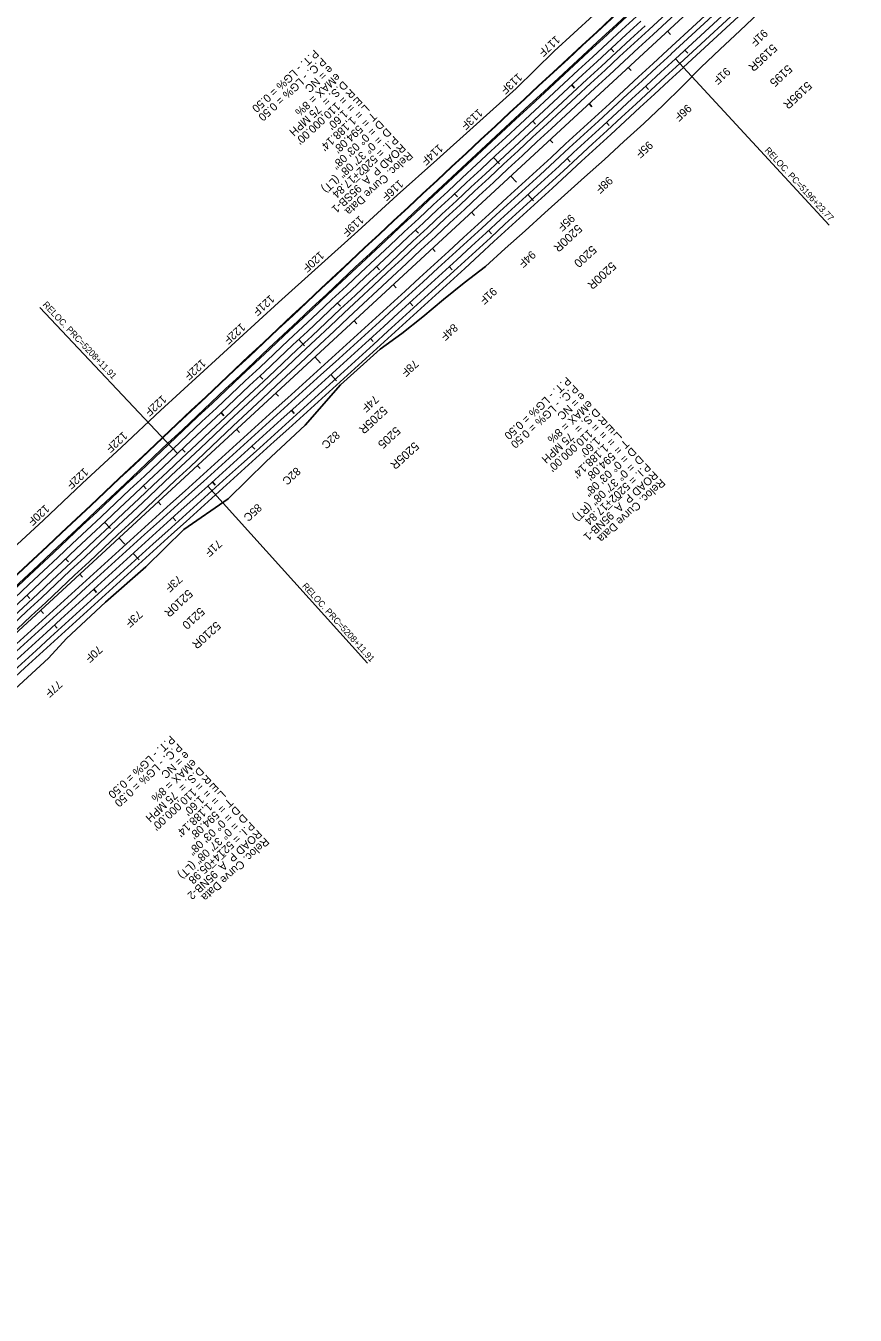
# Model space of a CAD drawing. Extents: x 2160876 to 2175625, y 601634 to 617693.
# Drawn here: x 2169242 to 2170797, y 609675 to 612093 of the extents above; entities that cross this region are included whole.
import ezdxf

# ---------------------------------------------------------------- set-up
doc = ezdxf.new("R2010")
doc.units = 0
for name, color, linetype in [('RD_HC_Cl', 7, 'Continuous'), ('RD_HC_CL_Rel', 7, 'Continuous'), ('RD_HC_Data_Rel', 7, 'Continuous'), ('RD_HC_Data_Tic', 7, 'Continuous'), ('RD_HC_Data_Tic_Rel', 7, 'Continuous'), ('RD_HC_TX_Rel_Sta50', 7, 'Continuous'), ('RD_HC_TX_Sta50', 7, 'Continuous'), ('RD_PD_CstnLmt', 7, 'Continuous'), ('RD_PD_Final_LnLine', 7, 'Continuous'), ('RD_PD_Final_TrvlWay', 7, 'Continuous'), ('RD_PD_GR', 7, 'Continuous'), ('RD_PD_MedBWall', 7, 'Continuous')]:
    doc.layers.add(name, color=color, linetype=linetype)

msp = doc.modelspace()

# ---------------------------------------------------------------- linework, layer by layer
at = {"layer": 'RD_HC_Cl'}
msp.add_line((2172239.9, 613739.9), (2163704.8, 605858.6), dxfattribs=at)
at = {"layer": 'RD_HC_CL_Rel'}
msp.add_line((2172272.5, 613704.6), (2170460.3, 612031.3), dxfattribs=at)
for centre, start, end in [((2245020.2, 531286.6), 132.719474, 133.338342), ((2095835.3, 692846.5), 312.100607, 312.719474), ((2094033.1, 691295.6), 312.719474, 313.338342), ((2243330.9, 529613.4), 132.100607, 132.719474)]:
    msp.add_arc(centre, 110000, start, end, dxfattribs=at)
at = {"layer": 'RD_HC_Data_Rel'}
for p, q in [((2170748.5, 611719.1), (2170460.3, 612031.3)), ((2169268.2, 611565), (2169526.6, 611291.1)), ((2169883, 610898), (2169583.1, 611230))]:
    msp.add_line(p, q, dxfattribs=at)
at = {"layer": 'RD_HC_Data_Tic'}
for p, q in [((2170445.2, 612082.7), (2170450.6, 612076.8)), ((2170371.7, 612014.8), (2170377.2, 612008.9)), ((2170298.3, 611947), (2170303.7, 611941.1)), ((2170224.8, 611879.1), (2170230.2, 611873.3)), ((2170151.3, 611811.3), (2170162.2, 611799.5)), ((2170077.9, 611743.5), (2170083.3, 611737.6)), ((2170004.4, 611675.6), (2170009.8, 611669.7)), ((2169930.9, 611607.8), (2169936.3, 611601.9)), ((2169857.5, 611539.9), (2169862.9, 611534.1)), ((2169784, 611472.1), (2169794.8, 611460.3)), ((2169710.5, 611404.2), (2169715.9, 611398.4)), ((2169637, 611336.4), (2169642.5, 611330.5)), ((2169563.6, 611268.6), (2169569, 611262.7)), ((2169490.1, 611200.7), (2169495.5, 611194.8)), ((2169416.6, 611132.9), (2169427.5, 611121.1)), ((2169343.2, 611065), (2169348.6, 611059.2)), ((2169269.7, 610997.2), (2169275.1, 610991.3))]:
    msp.add_line(p, q, dxfattribs=at)
at = {"layer": 'RD_HC_Data_Tic_Rel'}
for p, q in [((2170339.2, 612050.1), (2170344.6, 612044.2)), ((2170477.8, 612047.4), (2170483.2, 612041.5)), ((2170265.8, 611982.1), (2170271.2, 611976.3)), ((2170404.3, 611979.6), (2170409.7, 611973.7)), ((2170192.5, 611914.1), (2170197.9, 611908.3)), ((2170330.7, 611911.8), (2170336.2, 611905.9)), ((2170119.2, 611846.1), (2170130.1, 611834.4)), ((2170257.1, 611844.1), (2170262.5, 611838.2)), ((2170046, 611778), (2170051.4, 611772.1)), ((2170183.5, 611776.5), (2170194.3, 611764.7)), ((2169972.9, 611709.8), (2169978.3, 611703.9)), ((2170109.7, 611708.9), (2170115.1, 611703)), ((2169899.8, 611641.5), (2169905.2, 611635.7)), ((2170035.9, 611641.5), (2170041.3, 611635.6)), ((2169826.8, 611573.2), (2169832.2, 611567.3)), ((2169962.1, 611574), (2169967.5, 611568.1)), ((2169753.8, 611504.8), (2169764.7, 611493.1)), ((2169888.2, 611506.7), (2169893.6, 611500.8)), ((2169814.2, 611439.4), (2169824.9, 611427.6)), ((2169680.9, 611436.3), (2169686.4, 611430.5)), ((2169608.1, 611367.8), (2169613.6, 611362)), ((2169740.2, 611372.2), (2169745.5, 611366.3)), ((2169535.3, 611299.2), (2169540.8, 611293.4)), ((2169666.1, 611305), (2169671.4, 611299.1)), ((2169462.5, 611230.6), (2169468, 611224.8)), ((2169591.9, 611237.9), (2169597.3, 611232)), ((2169517.7, 611170.9), (2169523.1, 611164.9)), ((2169389.7, 611162.1), (2169400.7, 611150.4)), ((2169443.6, 611103.7), (2169454.4, 611091.9)), ((2169316.8, 611093.6), (2169322.3, 611087.8)), ((2169369.6, 611036.5), (2169374.9, 611030.6)), ((2169243.9, 611025.2), (2169249.4, 611019.4)), ((2169295.6, 610969.3), (2169301, 610963.3))]:
    msp.add_line(p, q, dxfattribs=at)
at = {"layer": 'RD_PD_CstnLmt'}
for p, q in [((2170306.3, 612112.7), (2170232.5, 612045.5)), ((2170232.5, 612045.5), (2170161.6, 611975.2)), ((2170161.6, 611975.2), (2170087.4, 611908.3)), ((2170087.4, 611908.3), (2170012.8, 611841.9)), ((2170012.8, 611841.9), (2169938.5, 611775.2)), ((2169938.5, 611775.2), (2169864.5, 611708)), ((2169864.5, 611708), (2169790, 611641.2)), ((2169790, 611641.2), (2169715.7, 611574.4)), ((2169715.7, 611574.4), (2169642.3, 611506.4)), ((2169642.3, 611506.4), (2169568.4, 611439.1)), ((2169568.4, 611439.1), (2169494.5, 611371.4)), ((2169494.5, 611371.4), (2169421.2, 611303.1)), ((2169421.2, 611303.1), (2169347.9, 611234.9)), ((2169347.9, 611234.9), (2169275, 611166.3)), ((2169275, 611166.3), (2169201.5, 611098.2))]:
    msp.add_line(p, q, dxfattribs=at)
for points in [[(2170617.1, 612117.6), (2170580.6, 612083.5), (2170544, 612049.4), (2170507.9, 612014.8), (2170472.7, 611979.1), (2170437.2, 611943.9), (2170400.6, 611909.8), (2170363.7, 611876.2)], [(2170363.7, 611876.2), (2170327.1, 611842), (2170289.4, 611809.1), (2170252.3, 611775.7), (2170215.2, 611742.1), (2170178.2, 611708.5), (2170140.8, 611675.3), (2170104, 611641.4), (2170064.2, 611610.8), (2170025, 611579.5), (2169986.6, 611547.5), (2169947.4, 611516.2)], [(2169947.4, 611516.2), (2169906.8, 611486.5), (2169832.2, 611419.8), (2169766.1, 611344.1), (2169692.9, 611276), (2169621.4, 611206), (2169538.3, 611148.5), (2169467, 611078.3), (2169391.8, 611012.4), (2169318.6, 610944.2), (2169284.7, 610907.2), (2169174, 610806.1), (2169099.5, 610739.3), (2169025.5, 610672), (2168948.7, 610607.8), (2168874.4, 610540.9), (2168798.4, 610475.8), (2168741.5, 610390), (2168667.6, 610322.7), (2168592.4, 610252), (2168544.5, 610187.1)]]:
    msp.add_lwpolyline(points, dxfattribs=at)
at = {"layer": 'RD_PD_Final_LnLine'}
for p, q in [((2172264.3, 613713.4), (2170452.2, 612040.1)), ((2172272.5, 613704.6), (2170460.3, 612031.3)), ((2172261.1, 613677.8), (2170468.4, 612022.5))]:
    msp.add_line(p, q, dxfattribs=at)
for centre, radius, start, end in [((2245020.2, 531286.6), 110041.3, 132.719474, 133.338342), ((2245020.2, 531286.6), 110040.3, 132.719474, 133.338342), ((2245020.2, 531286.6), 110012, 132.719474, 133.338342), ((2245020.2, 531286.6), 110000, 132.719474, 133.338342), ((2245020.2, 531286.6), 109988, 132.719474, 133.338342), ((2095835.3, 692846.5), 109988, 312.100607, 312.719474), ((2095835.3, 692846.5), 110000, 312.100607, 312.719474), ((2095835.3, 692846.5), 110012, 312.100607, 312.719474), ((2094033.1, 691295.6), 109958.7, 312.719474, 313.338342), ((2094033.1, 691295.6), 109959.7, 312.719474, 313.338342), ((2094033.1, 691295.6), 109988, 312.719474, 313.338342), ((2094033.1, 691295.6), 110000, 312.719474, 313.338342), ((2094033.1, 691295.6), 110012, 312.719474, 313.338342), ((2243330.9, 529613.4), 110012, 132.100607, 132.719474), ((2243330.9, 529613.4), 110000, 132.100607, 132.719474), ((2243330.9, 529613.4), 109988, 132.100607, 132.719474)]:
    msp.add_arc(centre, radius, start, end, dxfattribs=at)
at = {"layer": 'RD_PD_Final_TrvlWay'}
for p, q in [((2172222.2, 613759), (2170410.1, 612085.6)), ((2172257.5, 613720.8), (2170445.4, 612047.4)), ((2172287.4, 613688.4), (2170475.2, 612015.1))]:
    msp.add_line(p, q, dxfattribs=at)
for centre, radius, start, end in [((2245020.2, 531286.6), 110024, 132.719474, 133.338342), ((2245020.2, 531286.6), 109978, 132.719474, 133.338342), ((2095835.3, 692846.5), 109978, 312.100607, 312.719474), ((2095835.3, 692846.5), 110022, 312.100607, 312.719474), ((2094033.1, 691295.6), 109976, 312.719474, 313.338342), ((2094033.1, 691295.6), 110022, 312.719474, 313.338342), ((2243330.9, 529613.4), 110022, 132.100607, 132.719474), ((2243330.9, 529613.4), 109978, 132.100607, 132.719474)]:
    msp.add_arc(centre, radius, start, end, dxfattribs=at)
at = {"layer": 'RD_PD_GR'}
msp.add_line((2170418.2, 612076.8), (2171614.4, 613181.4), dxfattribs=at)
for centre, radius, start, end in [((2245020.2, 531286.6), 109966, 132.719474, 133.338342), ((2094033.1, 691295.6), 110034, 312.719474, 313.338342)]:
    msp.add_arc(centre, radius, start, end, dxfattribs=at)
at = {"layer": 'RD_PD_MedBWall'}
for centre, radius, start, end in [((2245020.2, 531286.6), 110026.3, 132.719474, 133.338342), ((2245020.2, 531286.6), 110024, 132.719474, 133.338342), ((2094033.1, 691295.6), 109973.7, 312.719474, 313.338342), ((2094033.1, 691295.6), 109976, 312.719474, 313.338342)]:
    msp.add_arc(centre, radius, start, end, dxfattribs=at)

# ---------------------------------------------------------------- texts
at = {"layer": 'RD_HC_Data_Rel'}
for s, height, rotation, p in [('P.T. - LG% = 0.50', 15, 222.7195, (2169783.2, 612049.3)), ('P.C. - LG% = 0.50', 15, 222.7195, (2169796.8, 612034.7)), ('e = NC', 15, 222.7195, (2169810.3, 612020)), ('eMAX = 8%', 15, 222.7195, (2169823.9, 612005.3)), ('D.S. =  75 MPH', 15, 222.7195, (2169837.5, 611990.6)), ("R = 110,000.00'", 15, 222.7195, (2169851, 611975.9)), ("L = 1,188.14'", 15, 222.7195, (2169878.2, 611946.5)), ("E = 1.60'", 15, 222.7195, (2169864.6, 611961.2)), ("T = 594.08'", 15, 222.7195, (2169891.7, 611931.8)), ('D = 0° 03\' 08"', 15, 222.7195, (2169905.3, 611917.1)), ('D', 15, 222.7195, (2169918.9, 611902.4)), ('    = 0° 37\' 08" (LT)', 15, 222.7195, (2169918.9, 611902.4)), ('ROAD P_A_95SB-1', 15, 222.7195, (2169946, 611873)), ('P.I. = 5202+17.84', 15, 222.7195, (2169932.4, 611887.7)), ('Reloc. Curve Data', 15, 222.7195, (2169959.6, 611858.3)), ('RELOC. PC=5196+23.77', 12, 312.7195, (2170626.6, 611858.7)), ('RELOC. PRC=5208+11.91', 12, 313.3383, (2169272.8, 611569.4)), ('P.T. - LG% = 0.50', 15, 222.7195, (2170256.4, 611435.9)), ('P.C. - LG% = 0.50', 15, 222.7195, (2170270, 611421.2)), ('eMAX = 8%', 15, 222.7195, (2170297.1, 611391.8)), ('e = NC', 15, 222.7195, (2170283.6, 611406.5)), ('D.S. =  75 MPH', 15, 222.7195, (2170310.7, 611377.1)), ("R = 110,000.00'", 15, 222.7195, (2170324.3, 611362.4)), ("E = 1.60'", 15, 222.7195, (2170337.8, 611347.7)), ("L = 1,188.14'", 15, 222.7195, (2170351.4, 611333)), ('D = 0° 03\' 08"', 15, 222.7195, (2170378.5, 611303.6)), ("T = 594.08'", 15, 222.7195, (2170365, 611318.3)), ('    = 0° 37\' 08" (RT)', 15, 222.7195, (2170392.1, 611288.9)), ('P.I. = 5202+17.84', 15, 222.7195, (2170405.7, 611274.2)), ('D', 15, 222.7195, (2170392.1, 611288.9)), ('ROAD P_A_95NB-1', 15, 222.7195, (2170419.2, 611259.5)), ('Reloc. Curve Data', 15, 222.7195, (2170432.8, 611244.8)), ('RELOC. PRC=5208+11.91', 12, 312.1006, (2169759.4, 611042)), ('P.T. - LG% = 0.50', 15, 222.7195, (2169513.7, 610763.2)), ('P.C. - LG% = 0.50', 15, 222.7195, (2169527.2, 610748.6)), ('eMAX = 8%', 15, 222.7195, (2169554.4, 610719.2)), ('e = NC', 15, 222.7195, (2169540.8, 610733.9)), ('D.S. =  75 MPH', 15, 222.7195, (2169568, 610704.5)), ("R = 110,000.00'", 15, 222.7195, (2169581.5, 610689.8)), ("E = 1.60'", 15, 222.7195, (2169595.1, 610675.1)), ("L = 1,188.14'", 15, 222.7195, (2169608.7, 610660.4)), ("T = 594.08'", 15, 222.7195, (2169622.2, 610645.7)), ('D = 0° 03\' 08"', 15, 222.7195, (2169635.8, 610631)), ('D', 15, 222.7195, (2169649.4, 610616.3)), ('    = 0° 37\' 08" (LT)', 15, 222.7195, (2169649.4, 610616.3)), ('P.I. = 5214+05.98', 15, 222.7195, (2169662.9, 610601.6)), ('ROAD P_A_95NB-2', 15, 222.7195, (2169676.5, 610586.9)), ('Reloc. Curve Data', 15, 222.7195, (2169690.1, 610572.2))]:
    msp.add_text(s, height=height, rotation=rotation, dxfattribs=at).set_placement(p)
at = {"layer": 'RD_HC_TX_Rel_Sta50'}
for s, rotation, p in [('5195R', 222.7195, (2170642, 612060.2)), ('5195R', 222.7195, (2170707.1, 611989.7)), ('5200R', 222.9154, (2170276.3, 611721.8)), ('5200R', 222.5235, (2170340.2, 611651.6)), ('5205R', 223.1759, (2169911.2, 611381)), ('5205R', 222.2631, (2169970.6, 611314)), ('5210R', 223.2404, (2169546.1, 611037.4)), ('5210R', 222.1986, (2169598.9, 610977.3))]:
    msp.add_text(s, height=16, rotation=rotation, dxfattribs=at).set_placement(p)
at = {"layer": 'RD_HC_TX_Sta50'}
for s, p in [('5195', (2170670.4, 612021.1)), ('5200', (2170303.4, 611682.2)), ('5205', (2169935.7, 611342.7)), ('5210', (2169568.7, 611003.8))]:
    msp.add_text(s, height=16, rotation=222.7195, dxfattribs=at).set_placement(p)
at = {"layer": 'RD_PD_CstnLmt'}
for s, rotation, p in [('117F', 222.5116, (2170235.7, 612075.6)), ('91F', 222.747, (2170624.9, 612087.7)), ('113F', 222.4331, (2170164.8, 612005.2)), ('91F', 222.6685, (2170554.9, 612015.9)), ('96F', 222.59, (2170482.1, 611947)), ('113F', 222.3546, (2170090.6, 611938.4)), ('95F', 222.5116, (2170409.6, 611877.9)), ('114F', 222.2761, (2170016.1, 611872)), ('116F', 222.2032, (2169941.9, 611805.2)), ('98F', 222.4331, (2170334.4, 611811.6)), ('119F', 222.2032, (2169867.8, 611738)), ('95F', 222.3546, (2170263.3, 611740.8)), ('120F', 222.2032, (2169793.4, 611671.3)), ('94F', 222.2761, (2170190, 611672.5)), ('121F', 222.2032, (2169700.3, 611589.6)), ('91F', 222.2032, (2170117.2, 611603.6)), ('122F', 222.2032, (2169645.7, 611536.4)), ('84F', 222.2032, (2170043.9, 611535.6)), ('122F', 222.2032, (2169571.7, 611469.1)), ('78F', 222.2032, (2169970.2, 611468)), ('122F', 222.2809, (2169497.8, 611401.5)), ('74F', 222.2032, (2169895.6, 611401.4)), ('122F', 222.3594, (2169424.5, 611333.2)), ('82C', 222.2032, (2169822.6, 611334.3)), ('122F', 222.4379, (2169351.1, 611265)), ('82C', 222.2032, (2169749.1, 611266.5)), ('120F', 222.5164, (2169278.2, 611196.3)), ('85C', 222.2809, (2169676.3, 611198.2)), ('71F', 222.3594, (2169601.8, 611130.6)), ('73F', 222.4379, (2169527.3, 611064.1)), ('73F', 222.5164, (2169452.6, 610998)), ('70F', 222.5949, (2169377.5, 610932.2)), ('77F', 222.6733, (2169302, 610866.9))]:
    msp.add_text(s, height=15, rotation=rotation, dxfattribs=at).set_placement(p)

doc.saveas('drawing.dxf')
